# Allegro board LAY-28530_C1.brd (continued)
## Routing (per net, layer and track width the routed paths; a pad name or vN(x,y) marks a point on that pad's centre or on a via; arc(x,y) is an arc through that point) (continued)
DDR4_BA0: length 137
  TOP w0.127: v2(130.32,19.3) 130.72,19.7 U35.K2 ; v2(158.26,19.3) 158.66,19.7 U37.K2
  TOP w0.152: v2(144.29,19.3) 144.69,19.7 U36.K2 ; v2(116.35,19.3) 116.75,19.7 U34.K2
  TOP w0.178: U21.AC21 132.2,56.81 131.88,56.81 131.37,56.31 131.37,51.74 v1(134.68,48.44)
  L4_INT2 w0.127: v1(167.7,20.62) 166.93,19.86 158.93,19.86 158.37,19.3 v2(158.26,19.3) 157.83,19.73 156.77,19.73 156.65,19.61 156.65,19.48 156.52,19.35 156.14,19.35 156.01,19.48 156.01,19.61 155.89,19.73 144.73,19.73 v2(144.29,19.3) 144.26,19.3 143.82,19.73 130.76,19.73 v2(130.32,19.3) 129.89,19.73 125.79,19.73 125.66,19.61 125.66,19.48 125.53,19.35 125.15,19.35 125.02,19.48 125.02,19.61 124.9,19.73 116.79,19.73 v2(116.35,19.3) 115.92,19.73 114.86,19.73
  L4_INT2 w0.178: 114.86,19.73 113.72,20.88 113.72,28.88 118.55,33.7 125.02,33.7 126.29,34.97 129.17,34.97 129.34,34.8 129.34,34.54 129.17,34.37 127.02,34.37 126.72,34.06 126.72,33.78 126.89,33.6 127.99,33.6 128.2,33.4 128.2,33.12 128.02,32.94 126.47,32.94 126.29,32.76 126.29,32.48 126.47,32.31 128.58,32.31 131.63,35.35 135.95,35.35 137.72,37.13 139.76,37.13 140.01,37.39 140.01,44.12 139.38,44.75 135.57,44.75 134.73,45.59 134.73,48.38 v1(134.68,48.44)
  BOTTOM w0.152: R383.2 168.84,20.11 168.2,20.11 v1(167.7,20.62)
DDR4_BA1: length 131.5
  TOP w0.127: U35.K8 135.52,19.7 v2(135.92,19.3) ; v2(163.86,19.3) 163.46,19.7 U37.K8 ; 133.41,54.66 133.41,56.42 133.8,56.81 U21.AA21
  TOP w0.152: U34.K8 121.55,19.7 v2(121.95,19.3) ; v2(149.89,19.3) 149.49,19.7 U36.K8 ; R173.2 v1(168.59,21.64)
  TOP w0.178: v1(133.79,54.02) 133.41,54.4 133.41,54.66
  L3_INT1 w0.127: 114.26,19.7 121.55,19.7 v2(121.95,19.3) 122.39,19.73 124.9,19.73 125.02,19.61 125.02,19.35 125.15,19.23 125.66,19.23 125.79,19.35 125.79,19.48 126.01,19.7 135.29,19.7 135.38,19.61 135.61,19.61 v2(135.92,19.3) 135.94,19.28 135.94,19.31 136.36,19.73 149.46,19.73 v2(149.89,19.3) 150.33,19.73 151.95,19.73 152.08,19.61 152.08,19.48 152.2,19.35 152.46,19.35 152.58,19.48 152.58,19.61 152.71,19.73 156.01,19.73 156.27,19.99 163.17,19.99 v2(163.86,19.3) 163.88,19.28 163.88,19.34 164.27,19.73 165.28,19.73 166.68,21.13 168.08,21.13 v1(168.59,21.64)
  L3_INT1 w0.178: 114.26,19.7 111.94,22.02 111.94,30.78 120.07,38.91 120.07,40.69 121.47,42.09 125.36,42.09 125.56,42.29 125.56,42.54 125.38,42.72 122.74,42.72 122.48,42.97 122.48,43.15 122.66,43.33 125.86,43.33 126.04,43.51 126.04,43.69 125.86,43.86 123.83,43.86 123.65,44.04 123.65,44.3 123.83,44.47 127.26,44.47 127.44,44.65 127.44,44.83 127.26,45.01 124.95,45.01 124.77,45.18 124.77,45.44 124.95,45.62 127.9,45.62 128.07,45.79 128.07,45.97 127.9,46.15 126.09,46.15 125.91,46.33 125.91,46.61 126.09,46.78 128.71,46.78 132.01,50.09 132.01,52.37 133.66,54.02 v1(133.79,54.02)
DDR4_BG0: length 137.3
  TOP w0.127: U37.J2 158.66,20.5 v2(159.06,20.9) ; U35.J2 130.72,20.5 v2(131.12,20.9) ; U34.J2 116.75,20.5 v2(117.15,20.9) ; v2(145.09,20.9) 144.69,20.5 U36.J2 ; U21.R18 138.6,59.21 v2(138.19,58.81)
  L4_INT2 w0.127: v2(138.19,58.81) 138.59,58.41 139.96,58.41 140.2,58.17 140.2,54.84 ; 114.61,21.23 114.61,21.13 115.25,20.5 116.75,20.5 v2(117.15,20.9) 117.64,21.38 119.94,21.38 120.85,20.48 130.7,20.48 v2(131.12,20.9) 131.61,21.38 133.66,21.38 134.55,20.5 U36.J2 v2(145.09,20.9) 145.58,21.38 147.5,21.38 148.39,20.5 U37.J2 v2(159.06,20.9) 159.06,21 159.44,21.38 161.73,21.38 162.62,20.5 165.54,20.5 v1(167.7,22.65)
  L4_INT2 w0.178: 114.61,21.23 114.61,27.73 118.04,31.16 126.88,31.16 127.06,30.99 127.06,30.73 126.88,30.55 124.31,30.55 124.14,30.38 124.14,30.2 124.31,30.02 127.95,30.02 132.26,34.34 136.33,34.34 138.11,36.12 140.52,36.12 141.03,36.62 141.03,45.13 140.39,45.77 136.07,45.77 135.82,46.02 135.82,48.05 136.96,49.2 138.87,49.2 139.38,49.71 139.38,54.02 140.2,54.84
  BOTTOM w0.152: v1(167.7,22.65) 168.2,22.15 168.84,22.15 R380.2
DDR4_BG1: length 131.8
  TOP w0.122: 121.58,20.5 121.57,20.5 U34.J8
  TOP w0.127: v2(137.4,58.81) 137.8,59.21 U21.T18 ; v2(135.92,20.9) 135.52,20.5 U35.J8 ; U36.J8 149.49,20.5 v2(149.89,20.9) ; 121.58,20.5 v2(121.95,20.88) ; v2(163.86,20.9) 163.46,20.5 U37.J8
  TOP w0.152: R170.2 v1(168.59,23.67)
  L3_INT1 w0.127: v1(168.59,23.67) 168.08,23.16 167.57,23.16 164.78,20.37 164.39,20.37 v2(163.86,20.9) 163.63,20.9 163.23,21.3 161.01,21.3 160.21,20.5 150.3,20.5 149.89,20.9 v2(149.89,20.9) 149.66,20.9 149.3,21.26 149.3,21.26 149.26,21.3 147.55,21.3 146.74,20.5 136.32,20.5 v2(135.92,20.9) 135.7,20.9 135.3,21.3 133.83,21.3 133.03,20.5 122.35,20.5 121.98,20.88 v2(121.95,20.88) 121.74,20.88 121.36,21.26 121.36,21.26 121.32,21.3 119.73,21.3 118.93,20.5 114.74,20.5 114.73,20.5 ; v2(137.4,58.81) 137.8,58.41 137.8,55.04
  L3_INT1 w0.178: 114.73,20.5 112.71,22.53 112.71,30.15 120.07,37.51 122.87,37.51 124.39,39.04 124.39,40.82 124.64,41.07 127.82,41.07 130.61,43.86 131.37,43.86 132.06,44.55 132.06,45.21 131.88,45.39 131.71,45.39 131.53,45.21 131.53,44.93 131.35,44.75 131.17,44.75 130.99,44.93 130.99,45.51 132.01,46.53 132.01,46.78 131.75,47.04 131.5,47.04 130.55,46.08 130.3,46.08 130.1,46.28 130.1,46.53 133.28,49.71 133.28,51.18 133.46,51.36 133.79,51.36 133.91,51.23 133.91,49.07 134.04,48.94 134.42,48.94 134.55,49.07 134.55,50.59 134.68,50.72 136.66,50.72 136.84,50.9 136.84,51.18 136.66,51.36 134.47,51.36 134.3,51.53 134.3,51.81 134.47,51.99 135.69,51.99 136.01,52.31 136.01,53.25 137.8,55.04
DDR4_CAS: length 156.5
  TOP w0.127: U37.H7 162.66,21.3 161.47,20.11 161.47,16.43 ; 119.69,16.18 119.69,17.96 119.56,18.08 119.56,20.11 120.75,21.3 U34.H7 ; v2(135,58.81) 135.4,59.21 U21.W18 ; U35.H7 134.72,21.3 133.53,20.11 133.53,16.56 133.66,16.43 ; U36.H7 148.69,21.3 147.5,20.11 147.5,15.8 147.76,15.54
  TOP w0.152: 147.76,15.54 147.76,14.17 147.91,14.02 v1(148.14,14.02) ; v1(119.94,14.02) 119.69,14.27 119.69,16.18 ; R183.2 v1(168.59,12.11) ; v1(133.66,14.02) 133.15,14.53 133.15,14.78 133.28,14.91 133.53,14.91 133.66,15.03 133.66,16.43 ; 161.47,16.43 v1(161.47,14.02)
  L3_INT1 w0.127: v1(168.59,12.11) 168.59,12.14 168.18,12.55 167.42,12.55 165.94,14.02 v1(161.47,14.02)
  L4_INT2 w0.127: v2(135,58.81) 134.6,58.41 132.9,58.41 132.48,58 ; v1(161.47,14.02) 160.71,14.02 160.58,13.89 160.58,13.76 160.46,13.64 160.08,13.64 159.95,13.76 159.95,13.89 159.82,14.02 159.31,14.02 159.19,13.89 159.19,13.64 159.06,13.51 158.81,13.51 158.68,13.64 158.68,13.89 158.55,14.02 157.79,14.02 157.16,14.65 152.58,14.65 151.95,14.02 v1(148.14,14.02) 144.84,14.02 144.2,14.65 138.74,14.65 138.11,14.02 v1(133.66,14.02) 133.53,13.89 128.83,13.89 128.2,14.53 122.36,14.53 121.85,14.02 v1(119.94,14.02)
  L4_INT2 w0.178: 132.48,58 128.67,54.19 128.67,50.94 126.17,48.44 126.17,44.55 125.99,44.37 125.74,44.37 125.56,44.55 125.56,44.68 125.38,44.85 125.1,44.85 124.93,44.68 124.93,43.64 124.14,42.85 115.25,42.85 113.72,41.32 113.72,35.74 109.15,31.16 109.15,19.35 114.48,14.02 v1(119.94,14.02)
DDR4_CS0: length 133.7
  TOP w0.127: U36.G7 v2(148.29,22.5) ; 131.76,55.93 131.76,56.11 132.06,56.41 132.6,56.41 133,56.81 U21.AB21 ; U35.G7 v2(134.32,22.5) ; U37.G7 v2(162.26,22.5) ; U34.G7 v2(120.35,22.5)
  TOP w0.178: v1(137.85,48.05) 137.22,48.69 135.31,48.69 131.76,52.25 131.76,55.93
  L4_INT2 w0.127: 117.55,27.63 117.55,22.89 117.94,22.5 ; v1(167.7,25.7) 167.19,25.19 166.93,25.19 164.64,22.9 162.66,22.9 v2(162.26,22.5) 154.52,22.5 154.36,22.65 154.36,22.78 154.23,22.91 153.85,22.91 153.73,22.78 153.73,22.63 153.6,22.5 151.6,22.5 151.19,22.9 148.69,22.9 v2(148.29,22.5) 147.88,22.91 145.27,22.91 145.26,22.9 134.72,22.9 v2(134.32,22.5) 131.35,22.5 130.95,22.9 126.29,22.9 126.17,22.77 126.17,22.65 126.04,22.53 125.79,22.53 125.66,22.65 125.66,22.77 125.53,22.9 120.75,22.9 v2(120.35,22.5)
  L4_INT2 w0.178: 117.94,22.5 v2(120.35,22.5) ; v1(137.85,48.05) 141.92,48.05 142.55,47.42 142.55,34.72 142.3,34.47 138.99,34.47 138.87,34.34 138.87,33.96 138.99,33.83 142.37,33.83 142.55,33.65 142.55,33.37 142.37,33.2 139.25,33.2 139.12,33.07 139.12,32.69 139.25,32.56 140.98,32.56 141.15,32.38 141.15,32.1 140.98,31.93 132.52,31.93 128.96,28.37 118.29,28.37 117.55,27.63
  BOTTOM w0.152: v1(167.7,25.7) 168.2,25.19 168.84,25.19 R376.2
DDR4_CS1: length 132.3
  TOP w0.127: U36.G8 v2(149.89,21.7) ; U34.G8 v2(121.95,21.7) ; U37.G8 v2(163.86,21.7) ; 131.44,58.4 131.82,58.79 133.38,58.79 133.8,59.21 U21.AA18 ; U35.G8 v2(135.92,21.7)
  TOP w0.152: R168.2 v1(168.59,25.7)
  TOP w0.178: 131.44,58.4 130.23,57.2 130.23,50.47 v1(132.77,47.93)
  L3_INT1 w0.127: v1(168.59,25.7) 168.08,25.19 167.32,25.19 166.81,24.69 166.81,23.92 164.98,22.1 164.26,22.1 v2(163.86,21.7) U37.G8 159.26,22.1 159.24,22.11 150.87,22.11 150.86,22.1 150.53,22.1 150.51,22.11 150.31,22.11 v2(149.89,21.7) 149.49,22.1 139.63,22.1 139.5,21.97 139.5,21.89 139.38,21.77 139.12,21.77 139,21.88 139,22.01 138.91,22.1 136.32,22.1 135.94,21.71 135.94,21.68 v2(135.92,21.7) 135.47,22.15 135.33,22.15 135.29,22.1 134.96,22.1 134.91,22.15 134.53,22.15 134.49,22.1 134.16,22.1 134.11,22.15 125.58,22.15 125.41,21.97 125.41,21.89 125.28,21.77 124.9,21.77 124.78,21.88 124.78,21.97 124.65,22.1 122.35,22.1 v2(121.95,21.7) U34.G8 114.79,22.1
  L3_INT1 w0.178: 114.79,22.1 113.47,23.42 113.47,29.64 119.16,35.33 123.96,35.33 124.14,35.51 124.14,35.68 123.96,35.86 120.38,35.86 120.2,36.04 120.2,36.32 120.38,36.5 123.5,36.5 124.87,37.87 127.39,37.87 127.56,38.05 127.56,38.22 127.39,38.4 125.84,38.4 125.66,38.58 125.66,38.81 125.84,38.99 128.66,38.99 128.83,39.16 128.83,39.34 128.66,39.52 125.84,39.52 125.66,39.7 125.66,39.88 125.84,40.05 128.58,40.05 131.37,42.85 131.88,42.85 133.28,44.24 133.28,47.42 v1(132.77,47.93)
DDR4_DM0: length 46
  TOP w0.127: U37.A7 v2(162.26,27.3)
  TOP w0.178: U21.A21 152.33,54.27 152.33,48.82 154.62,46.53 154.62,44.88 155.38,44.12 155.38,39.67 155.5,39.55 155.89,39.55 156.01,39.67 156.01,44.57 156.19,44.75 156.47,44.75 156.65,44.57 156.65,39.93 159.25,37.32 159.25,36.43 160.71,34.97 160.71,30.43 v1(162.26,28.88)
  L3_INT1 w0.178: v2(162.26,27.3) v1(162.26,28.88)
DDR4_DM1: length 40.5
  TOP w0.109: U21.E21 146.6,56.81 v2(147,56.41)
  TOP w0.127: U36.A7 v2(148.29,27.3)
  L3_INT1 w0.178: v2(148.29,27.3) 147.88,27.71 147.88,31.8 148.01,31.93 148.77,31.93 148.9,32.05 148.9,35.3 148.72,35.48 148.39,35.48 148.27,35.35 148.27,32.64 148.09,32.46 147.91,32.46 147.73,32.64 147.73,35.84 147.88,35.99 148.77,35.99 148.9,36.12 148.9,47.55 148.27,48.18 148.27,49.96 148.9,50.59 148.9,51.03 148.7,51.23 148.52,51.23 148.27,51.48 148.27,53.13 147.5,53.9 147.5,55.93 147.02,56.41 v2(147,56.41)
DDR4_DM2: length 41.2
  TOP w0.127: U21.H22 144.2,56.01 144.59,55.62 144.59,54.69 ; U35.A7 v2(134.32,27.3)
  TOP w0.178: 144.59,54.69 144.59,40.82 142.17,38.4 141.92,38.4 141.72,38.6 141.72,38.84 142.3,39.42 142.3,39.55 142.04,39.8 141.66,39.8 135.31,33.45 135.06,33.45 134.93,33.32 134.93,33.07 135.06,32.94 135.82,32.94 135.95,32.81 135.95,32.56 135.82,32.43 134.68,32.43 134.55,32.31 134.55,32.05 134.68,31.93 135.69,31.93 135.95,31.67 v1(135.95,31.29)
  L3_INT1 w0.178: v1(135.95,31.29) 135.95,31.16 135.44,30.66 135.44,28.72 134.32,27.61 v2(134.32,27.3)
DDR4_DM3: length 51.7
  TOP w0.127: U21.L20 141.8,57.61 v2(142.2,57.21) ; U34.A7 v2(120.35,27.3)
  L3_INT1 w0.127: 123.75,26.9 122.92,26.9 122.92,26.9 U34.A7 v2(120.35,27.3) ; 142.6,55.04 142.6,56.81 v2(142.2,57.21)
  L3_INT1 w0.178: 123.75,26.9 125.97,26.9 131.88,32.81 133.79,32.81 142.42,41.45 142.42,41.7 142.23,41.9 141.98,41.9 140.14,40.05 139.88,40.05 139.63,40.31 139.63,40.56 142.6,43.53 142.6,55.04
DDR4_DQ0: length 46.3
  TOP w0.127: U37.C2 v2(159.06,24.9)
  TOP w0.178: U21.A19 149.86,58.34 150.93,58.34 156.01,53.26 156.01,52.75 155.89,52.63 155.5,52.63 155.38,52.5 155.38,52.12 155.5,51.99 155.89,51.99 156.01,51.86 156.01,51.61 155.76,51.36 155.63,51.36 155.38,51.1 155.38,49.71 161.85,43.23 161.85,38.28 163.76,36.37 163.76,31.04 v1(162.87,30.15)
  L3_INT1 w0.178: v2(159.06,24.9) 159.53,24.43 161.85,24.43 162.87,25.45 v1(162.87,30.15)
DDR4_DQ1: length 46.4
  TOP w0.127: 150.42,56.82 150.04,57.2 148.61,57.2 U21.C20 ; U37.B7 v2(162.26,26.5)
  TOP w0.178: 150.42,56.82 152.96,54.28 152.96,49.07 157.28,44.75 157.28,40.18 157.46,40 157.74,40 157.92,40.18 157.92,43.69 158.1,43.86 158.38,43.86 158.55,43.69 158.55,39.29 159.82,38.02 159.82,36.88 161.35,35.35 161.35,30.66 v1(161.73,30.27)
  L3_INT1 w0.178: v2(162.26,26.5) 161.73,27.03 v1(161.73,30.27)
DDR4_DQ2: length 46.1
  TOP w0.127: U37.D3 v2(159.86,24.9)
  TOP w0.178: U21.C23 150.93,52.47 150.93,48.31 151.69,47.55 151.69,44.37 151.82,44.24 152.2,44.24 152.33,44.37 152.33,46.23 152.51,46.4 152.79,46.4 152.96,46.23 152.96,39.8 153.35,39.42 153.98,39.42 155.5,37.89 155.5,37.39 156.78,36.11 157.03,36.11 157.29,36.37 157.29,36.62 156.33,37.58 156.33,37.83 156.52,38.02 156.77,38.02 158.04,36.75 158.04,35.61 159.19,34.47 159.19,29.39 v1(159.95,28.62)
  L3_INT1 w0.178: v1(159.95,28.62) 160.33,28.24 160.33,25.37 v2(159.86,24.9)
DDR4_DQ3: length 46.1
  TOP w0.178: U37.D7 162.42,24.5 160.84,26.08 160.84,26.97 159.06,28.75 v1(157.03,28.75) ; U21.D23 147.39,55.21 147.39,54.01 149.28,52.12 149.28,48.05 150.55,46.78 150.55,40.23 150.73,40.05 151.01,40.05 151.19,40.23 151.19,41.53 151.36,41.7 151.69,41.7 151.82,41.58 151.82,37.39 154.23,34.97 155.33,34.97 155.63,34.67 155.63,33.45 155.76,33.32 156.14,33.32 156.27,33.45 156.27,34.67 156.44,34.85 156.72,34.85 156.9,34.67 v1(156.9,32.18)
  L3_INT1 w0.178: v1(157.03,28.75) 156.9,28.88 v1(156.9,32.18)
DDR4_DQ4: length 46.5
  TOP w0.127: U37.D2 v2(159.06,24.1) ; U21.B19 149.4,58 150.3,58
  TOP w0.178: v1(163,31.93) 163,35.86 161.09,37.77 161.09,42.85 154.74,49.2 154.74,53.77 150.51,58 150.3,58
  L3_INT1 w0.127: v2(159.06,24.1) 159.11,24.05 163.12,24.05 164.26,25.19 164.26,27.86 164.27,27.86
  L3_INT1 w0.178: 164.27,27.86 164.27,28.12 163.89,28.5 163.89,31.04 v1(163,31.93)
DDR4_DQ5: length 46.3
  TOP w0.127: U37.D8 v2(163.06,24.9)
  TOP w0.178: U21.A20 149.8,57.61 150.27,57.61 154.11,53.77 154.11,48.82 159.06,43.86 159.06,39.67 159.19,39.55 159.57,39.55 159.7,39.67 159.7,42.67 159.87,42.85 160.22,42.85 160.39,42.67 160.39,37.32 162.24,35.48 162.24,31.8 v1(163,31.04)
  L3_INT1 w0.178: v1(163,31.04) 163.38,30.66 163.38,25.22 v2(163.06,24.9)
DDR4_DQ6: length 46
  TOP w0.127: v2(160.71,24.95) U37.E3
  TOP w0.178: v1(159.95,29.64) 159.95,34.72 158.68,35.99 158.68,37.01 156.9,38.78 155.38,38.78 154.74,39.42 154.74,43.94 154.57,44.12 154.29,44.12 154.11,43.94 154.11,40.31 153.98,40.18 153.6,40.18 153.47,40.31 153.47,46.66 151.57,48.56 151.57,52.64 U21.B23
  L3_INT1 w0.178: v2(160.71,24.95) 160.71,28.88 v1(159.95,29.64)
DDR4_DQ7: length 46
  TOP w0.127: U21.D22 147.39,56.01 147.79,55.62 147.79,54.66
  TOP w0.178: U37.E7 160.46,25.9 160.46,26.72 159.06,28.12 v1(158.3,28.12) ; 147.79,54.66 147.79,54.4 150.3,51.9 150.3,48.18 151.19,47.29 151.19,43.86 152.33,42.72 152.33,37.77 154.36,35.73 154.61,35.73 154.87,35.99 154.87,36.24 153.35,37.77 153.35,38.02 153.54,38.21 153.79,38.21 156.52,35.48 157.16,35.48 157.79,34.85 v1(157.79,32.69)
  L3_INT1 w0.178: v1(158.3,28.12) 157.79,28.62 v1(157.79,32.69)
DDR4_DQ8: length 40.6
  TOP w0.109: U21.C21 v2(148.6,56.41)
  TOP w0.127: U36.C2 v2(144.29,24.9)
  L3_INT1 w0.127: v2(148.6,56.41) 148.2,56.01 148.2,55.11 ; v2(144.29,24.9) 144.69,24.5 145.26,24.5 145.32,24.43 149.19,24.43 149.49,24.73 149.49,25.19
  L3_INT1 w0.178: 148.2,55.11 148.52,54.79 148.52,54.4 149.79,53.13 149.79,52.75 149.66,52.63 149.41,52.63 149.28,52.5 149.28,52.12 149.41,51.99 149.66,51.99 149.79,51.86 149.79,49.96 149.28,49.45 149.28,48.56 149.79,48.05 149.79,28.37 149.28,27.86 149.28,25.4 149.49,25.19
DDR4_DQ9: length 40.5
  TOP w0.127: U36.B7 v2(148.29,26.5)
  TOP w0.152: v2(147,57.21) 146.99,57.21 U21.E20
  L3_INT1 w0.127: 147,57.2 146.6,56.8 146.6,55.06
  L3_INT1 w0.178: v2(148.29,26.5) 147.25,27.54 147.25,36.24 147.5,36.5 148.14,36.5 148.39,36.75 148.39,39.04 148.27,39.16 147.88,39.16 147.76,39.04 147.76,37.16 147.58,36.98 147.4,36.98 147.22,37.16 147.22,39.67 147.35,39.8 148.27,39.8 148.39,39.93 148.39,47.29 147.76,47.93 147.76,50.21 148.14,50.59 148.14,50.98 147.76,51.36 147.76,52.88 147,53.64 147,54.66 146.6,55.06 ; v2(147,57.21) 147,57.2
DDR4_DQ10: length 40.5
  TOP w0.127: U36.D3 v2(145.09,24.9) ; U21.H21 144.2,56.81 v2(144.6,56.41)
  L3_INT1 w0.127: 145.09,54.91 144.74,55.27 144.74,56.27 v2(144.6,56.41)
  L3_INT1 w0.178: 145.09,54.91 145.09,53.13 145.98,52.25 145.98,47.17 146.36,46.78 146.36,45.82 146.18,45.64 145.47,45.64 144.96,45.13 144.96,39.8 145.34,39.42 145.34,33.45 145.22,33.32 144.2,33.32 144.07,33.2 144.07,31.09 144.25,30.91 144.53,30.91 144.71,31.09 144.71,32.69 144.84,32.81 145.22,32.81 145.34,32.69 145.34,27.73 145.09,27.48 v2(145.09,24.9)
DDR4_DQ11: length 40.7
  TOP w0.127: v2(143.8,56.41) 143.4,56.81 U21.J21
  TOP w0.178: v2(143.95,28.62) 145.22,28.62 147.76,26.08 147.76,25.43 U36.D7
  L3_INT1 w0.127: v2(143.8,56.41) 143.8,56.17 144.2,55.77 144.2,55.04 143.95,54.79
  L3_INT1 w0.178: 143.95,54.79 143.95,52.63 144.96,51.61 144.96,46.91 143.95,45.9 143.95,39.29 144.33,38.91 144.33,35.53 144.15,35.35 143.87,35.35 143.69,35.53 143.69,36.5 143.57,36.62 143.19,36.62 143.06,36.5 143.06,34.08 142.55,33.58 142.55,30.99 143.95,29.59 v2(143.95,28.62)
DDR4_DQ12: length 40.8
  TOP w0.127: v2(147.8,58.01) 147.4,58.41 147.39,58.41 U21.D19 ; U36.D2 v2(145.09,24.1)
  L3_INT1 w0.127: 149,55.04 149,56.81 v2(147.8,58.01) ; v2(145.09,24.1) 145.14,24.05 149.28,24.05 150.29,25.07 150.29,27.73
  L3_INT1 w0.178: 150.29,27.73 150.29,53.39 149,54.69 149,55.04
DDR4_DQ13: length 40.6
  TOP w0.109: U21.D21 147.39,56.81 147.4,56.81 v2(147.8,56.41)
  TOP w0.127: U36.D8 v2(149.09,24.9)
  L3_INT1 w0.178: v2(149.09,24.9) 148.77,25.22 148.77,27.99 149.41,28.62 149.41,30.78 149.28,30.91 149.03,30.91 148.9,30.78 148.9,28.7 148.72,28.52 148.55,28.52 148.37,28.7 148.37,31.18 148.6,31.42 149.28,31.42 149.41,31.54 149.41,47.8 148.77,48.44 148.77,49.71 149.28,50.21 149.28,51.48 149.15,51.61 148.9,51.61 148.77,51.74 148.77,53.39 147.88,54.28 147.88,56.32 v2(147.8,56.41)
DDR4_DQ14: length 40.6
  TOP w0.127: U36.E3 v2(146.74,24.95)
  TOP w0.152: U21.G20 145,57.61 v2(144.6,57.21)
  L3_INT1 w0.127: 145.47,54.91 145,55.39 145,56.81 v2(144.6,57.21) ; 145.49,25.18 145.85,24.81 146.6,24.81 v2(146.74,24.95)
  L3_INT1 w0.178: 145.47,54.91 145.49,54.89 145.49,53.37 146.49,52.37 146.49,47.29 147,46.78 147,43.91 146.82,43.74 146.54,43.74 146.36,43.91 146.36,44.83 146.18,45.01 145.85,45.01 145.73,44.88 145.73,43.21 145.49,42.97 145.49,39.91 145.85,39.55 145.85,27.59 145.49,27.23 145.49,25.18
DDR4_DQ15: length 40.5
  TOP w0.152: v2(143.8,57.21) 143.4,57.61 U21.J20
  TOP w0.178: v1(144.58,27.99) 145.22,27.99 147.25,25.96 147.25,25.14 U36.E7
  L3_INT1 w0.127: 144.46,54.91 144.46,55.98 144.2,56.24 144.2,56.57 144.2,56.58 144.2,56.8 v2(143.8,57.21)
  L3_INT1 w0.178: v1(144.58,27.99) 144.58,29.77 143.38,30.97 143.38,33.51 143.69,33.83 143.69,34.47 143.82,34.59 144.18,34.59 144.3,34.47 144.3,34.26 144.48,34.08 144.66,34.08 144.84,34.26 144.84,39.16 144.46,39.55 144.46,45.51 145.09,46.15 145.6,46.15 145.85,46.4 145.85,46.66 145.47,47.04 145.47,51.86 144.46,52.88 144.46,54.91
DDR4_DQ16: length 41.6
  TOP w0.127: U35.C2 v2(130.32,24.9) ; 146.2,54.66 146.2,55.6 145.8,56.01 U21.F22
  TOP w0.178: 146.2,54.66 146.2,39.89 136.71,30.4 v1(135.95,30.4)
  L3_INT1 w0.127: v2(130.32,24.9) 130.32,24.85 130.67,24.5 131.57,24.5
  L3_INT1 w0.178: v1(135.95,30.4) 135.95,28.62 134.93,27.61 134.93,25.58 133.76,24.41 131.66,24.41 131.57,24.5
DDR4_DQ17: length 41.5
  TOP w0.127: U35.B7 v2(134.32,26.5)
  TOP w0.178: U21.G23 145,55.21 145.09,55.12 145.09,40.56 139.88,35.35 139.63,35.35 139.44,35.55 139.44,35.8 141.28,37.64 141.28,37.77 140.96,38.09 140.71,38.09 136.71,34.08 v1(136.71,32.81)
  L3_INT1 w0.178: v2(134.32,26.5) 133.79,27.03 133.79,27.75 134.93,28.9 134.93,31.04 v1(136.71,32.81)
DDR4_DQ18: length 41.1
  TOP w0.127: U35.D3 v2(131.12,24.9)
  TOP w0.178: v1(131.76,30.15) 131.76,30.53 132.01,30.78 132.39,30.78 132.52,30.91 132.52,31.29 132.39,31.42 131.88,31.42 131.76,31.54 131.76,31.93 131.88,32.05 132.26,32.05 132.39,32.18 132.39,32.43 132.26,32.56 131.88,32.56 131.76,32.69 131.76,33.07 131.88,33.2 132.26,33.2 132.39,33.32 132.39,33.7 132.26,33.83 131.88,33.83 131.76,33.96 131.76,35.86 133.15,37.26 135.82,37.26 140.52,41.96 141.92,41.96 142.42,42.47 142.42,55.04 142.6,55.21 U21.K23
  L3_INT1 w0.127: v1(131.76,30.15) 131.76,26.97 131.12,26.34 v2(131.12,24.9)
DDR4_DQ19: length 41.2
  TOP w0.127: 141.38,54.81 141.38,55.63 141,56.01 U21.M22
  TOP w0.178: 141.38,54.81 141.38,46.12 140.65,45.39 140.65,43.1 140.52,42.97 139.63,42.97 135.18,38.53 132.14,38.53 130.49,36.88 130.49,29.26 130.59,29.16 v1(130.59,29.12) ; U35.D7 133.66,25.56 133.66,26.46 132.14,27.99 130.65,27.99 v2(130.61,27.95)
  L3_INT1 w0.127: v1(130.59,29.12) 130.59,28.01 130.61,27.99 v2(130.61,27.95)
DDR4_DQ20: length 41.2
  TOP w0.127: U35.D2 v2(131.12,24.1)
  TOP w0.178: v1(136.84,29.64) 145.47,38.28 146.36,38.28 146.87,38.78 146.87,54.94 146.6,55.21 U21.E23
  L3_INT1 w0.127: 136.32,27.73 136.32,25.32 135.06,24.05 131.17,24.05 v2(131.12,24.1)
  L3_INT1 w0.178: v1(136.84,29.64) 136.84,28.24 136.32,27.73
DDR4_DQ21: length 41.3
  TOP w0.127: U35.D8 v2(135.12,24.9)
  TOP w0.178: U21.F23 145.8,55.21 145.6,55.01 145.6,40.18 138.23,32.81 137.98,32.81 137.72,33.07 137.72,33.32 139.12,34.72 139.12,34.85 138.87,35.1 138.61,35.1 137.22,33.7 137.22,31.67 v1(136.84,31.29)
  L3_INT1 w0.178: v1(136.84,31.29) 136.84,30.53 136.33,30.02 136.33,28.5 135.44,27.61 135.44,25.22 v2(135.12,24.9)
DDR4_DQ22: length 41.2
  TOP w0.127: U35.E3 132.63,24.81 132.75,24.81 v2(132.77,24.83) ; U21.K22 142.6,56.01 143,55.6 143,54.53
  TOP w0.178: 143,54.53 143,41.78 142.55,41.32 140.77,41.32 136.07,36.62 133.79,36.62 133.03,35.86 133.03,29.89 v1(132.26,29.13)
  L3_INT1 w0.127: v2(132.77,24.83) 131.87,24.83 131.53,25.17 131.53,26.24 132.26,26.97 v1(132.26,29.13)
DDR4_DQ23: length 41.3
  TOP w0.178: v1(131.21,29.46) 131.21,29.55 131.12,29.64 131.12,36.37 132.64,37.89 135.57,37.89 140.14,42.47 141.41,42.47 141.92,42.97 141.92,44.63 141.79,44.75 141.41,44.75 141.28,44.88 141.28,45.26 141.41,45.39 141.66,45.39 141.92,45.64 141.92,55.09 141.8,55.21 U21.L23 ; v2(131.21,27.48) 131.88,27.48 133.15,26.21 133.15,25.27 U35.E7
  L3_INT1 w0.127: v1(131.21,29.46) v2(131.21,27.48)
DDR4_DQ24: length 51.4
  TOP w0.127: U34.C2 v2(116.35,24.9) ; U21.K21 142.6,56.81 v2(143,56.41)
  L3_INT1 w0.127: v2(116.35,24.9) 116.35,24.85 116.7,24.5 117.59,24.5 117.68,24.41 121.32,24.41 122.21,25.3 123.23,25.3
  L3_INT1 w0.178: 123.23,25.3 123.61,25.3 123.75,25.45 123.75,25.96 123.88,26.08 124.26,26.08 124.39,25.96 124.39,25.43 124.52,25.3 125.13,25.3 132.14,32.31 134.04,32.31 143,41.26 v2(143,56.41)
DDR4_DQ25: length 51.6
  TOP w0.127: v2(142.2,56.41) 141.8,56.81 U21.L21
  TOP w0.152: U34.B7 v2(120.35,26.5)
  L3_INT1 w0.127: 142.2,56.33 142.2,56.21 141.66,55.67
  L3_INT1 w0.178: v2(142.2,56.41) 142.2,56.33 ; 141.66,55.67 141.66,43.36 136.58,38.27 136.58,38.02 136.84,37.77 136.96,37.77 138.93,39.74 139.18,39.74 139.38,39.54 139.38,39.29 133.41,33.32 131.63,33.32 126.17,27.86 120.07,27.86 119.82,27.61 119.82,27.03 v2(120.35,26.5)
DDR4_DQ26: length 51.7
  TOP w0.127: U34.D3 v2(117.15,24.9) ; U21.N21 140.2,56.81 v2(139.8,56.41)
  L3_INT1 w0.178: v2(139.8,56.41) 139.8,54.95 139.25,54.4 139.25,44.5 138.99,44.24 138.82,44.24 138.64,44.42 138.64,45.08 138.46,45.26 138.28,45.26 138.11,45.08 138.11,43.48 132.9,38.28 132.9,36.62 132.2,35.93 130.55,35.93 125.91,31.29 124.52,31.29 124.39,31.42 124.39,31.67 124.26,31.8 123.88,31.8 123.75,31.67 123.75,31.42 123.63,31.29 123.25,31.29 123.12,31.42 123.12,31.8 122.99,31.93 122.61,31.93 122.48,31.8 122.48,31.42 122.36,31.29 121.98,31.29 121.85,31.42 121.85,31.75 121.67,31.93 121.34,31.93 121.21,31.8 121.21,31.54 120.96,31.29 119.31,31.29 117.53,29.51 117.53,27.1 117.15,26.72 v2(117.15,24.9)
DDR4_DQ27: length 51.6
  TOP w0.127: v2(138.99,56.41) 139.4,56.81 U21.P21
  TOP w0.178: v2(117.02,27.48) 116.52,27.99 116.52,28.5 116.77,28.75 117.53,28.75 119.56,26.72 119.56,25.69 U34.D7
  L3_INT1 w0.127: v2(138.99,56.41) 138.6,56.01 138.6,55.28 138.36,55.04
  L3_INT1 w0.178: v2(117.02,27.48) 116.52,27.99 116.52,29.77 119.82,33.07 126.04,33.07 129.85,36.88 130.36,36.88 130.74,37.26 130.74,37.51 130.61,37.64 130.61,37.89 130.74,38.02 130.99,38.02 131.12,37.89 131.5,37.89 131.76,38.15 131.76,38.78 137.03,44.05 137.03,48.5 138.36,49.83 138.36,55.04
DDR4_DQ28: length 51.7
  TOP w0.127: v2(143,58.01) 142.6,58.41 U21.K19 ; U34.D2 v2(117.15,24.1)
  L3_INT1 w0.127: 123.18,24.5 121.73,24.5 121.28,24.05 117.2,24.05 v2(117.15,24.1) ; v2(143,58.01) 143.39,57.61 143.39,55.17 143.4,55.17
  L3_INT1 w0.178: 143.4,55.17 143.4,40.77 134.42,31.8 132.52,31.8 125.22,24.5 123.18,24.5
DDR4_DQ29: length 51.7
  TOP w0.127: U21.L19 141.8,58.41 v2(142.2,58.01) ; U34.D8 v2(121.15,24.9)
  L3_INT1 w0.127: 141.28,55.67 141.79,56.18 141.79,57.6 v2(142.2,58.01)
  L3_INT1 w0.178: v2(121.15,24.9) 120.49,24.9 119.44,25.96 119.44,27.86 119.94,28.37 125.79,28.37 131.37,33.96 133.15,33.96 136.2,37.01 136.2,37.26 136.01,37.45 135.76,37.45 135.25,36.94 134.99,36.94 134.8,37.13 134.8,37.39 141.28,43.86 141.28,55.67
DDR4_DQ30: length 51.7
  TOP w0.127: v2(118.93,24.81) 118.66,24.81 U34.E3 ; v2(139.8,57.21) 140.2,57.61 U21.N20
  L3_INT1 w0.127: v2(139.8,57.21) 140.2,56.81 140.2,55.55 140.19,55.55
  L3_INT1 w0.178: 140.19,55.55 140.19,54.71 139.63,54.15 139.63,44.24 133.41,38.02 133.41,36.24 132.58,35.42 130.8,35.42 126.04,30.66 120.58,30.66 120.45,30.53 120.45,30.02 120.33,29.89 119.82,29.89 119.69,30.02 119.69,30.53 119.56,30.66 119.31,30.66 117.91,29.26 117.91,26.97 117.55,26.61 117.55,25.18 117.91,24.81 v2(118.93,24.81)
DDR4_DQ31: length 51.6
  TOP w0.127: U21.N19 140.2,58.41 v2(139.8,58.01)
  TOP w0.178: v2(117.02,28.12) 117.4,28.12 118.93,26.59 118.93,25.52 U34.E7
  L3_INT1 w0.127: 139.8,58 139.39,57.6 139.39,55.44 139.38,55.43 139.38,55.17
  L3_INT1 w0.178: 139.38,55.17 138.87,54.66 138.87,48.31 137.72,47.17 137.72,46.66 137.85,46.53 138.36,46.53 138.49,46.4 138.49,46.02 138.36,45.9 137.85,45.9 137.6,45.64 137.6,43.74 132.39,38.53 132.39,37.64 131.12,36.37 130.23,36.37 126.29,32.43 119.82,32.43 117.02,29.64 v2(117.02,28.12) ; v2(139.8,58.01) 139.8,58
DDR4_DQS0: length 46.1
  TOP w0.127: U37.C3 v2(159.86,25.7)
  TOP w0.152: U21.B22 v2(149.4,55.61)
  L3_INT1 w0.129: v2(149.4,55.61) 149.67,55.89 150.11,55.89 150.37,55.63 150.38,55.63 151.83,54.18 151.82,54.17 151.82,44.27 152.1,44 152.68,44 152.95,44.27 152.95,48.44 153.08,48.57 153.48,48.57 153.61,48.44 153.61,44.27 159.03,38.85 159.03,27.74 159.02,27.73 159.02,26.25 159.22,26.04 159.23,26.04 159.3,25.98 159.58,25.98 v2(159.86,25.7)
DDR4_DQS0_N: length 46
  TOP w0.109: U21.B21 v2(149.4,56.41)
  TOP w0.127: U37.B3 v2(159.86,26.5)
  L3_INT1 w0.129: v2(159.86,26.5) 159.58,26.22 159.4,26.22 159.27,26.35 159.27,38.95 153.85,44.37 153.85,48.54 153.58,48.82 152.98,48.82 152.71,48.54 152.71,44.4 152.58,44.27 152.21,44.27 152.08,44.4 152.08,54.28 150.22,56.13 149.67,56.13 v2(149.4,56.41)
DDR4_DQS1: length 40.6
  TOP w0.127: U36.C3 v2(146.08,25.3) ; U21.G21 145,56.81 v2(145.4,57.21)
  L3_INT1 w0.127: v2(146.08,25.3) 146.35,25.58 147.09,25.58 147.37,25.86 147.37,26.31
  L3_INT1 w0.129: v2(145.4,57.21) 145.65,56.96 145.88,56.96 146.23,56.6 146.23,54.66 146.36,54.53 146.36,53.51 147.25,52.63 147.25,47.67 147.88,47.04 147.88,41.09 147.61,40.82 147.14,40.82 146.87,41.09 146.87,42.59 146.74,42.72 146.49,42.72 146.36,42.59 146.36,40.18 146.6,39.94 146.6,27.24 146.74,27.1 146.99,27.1 147.37,26.72 147.37,26.31
DDR4_DQS1_N: length 40.7
  TOP w0.127: U36.B3 v2(146.08,26.1)
  TOP w0.152: v2(145.4,56.41) 145.8,56.81 U21.F21
  L3_INT1 w0.127: v2(146.08,26.1) 146.35,25.82 146.99,25.82 147.12,25.96 147.12,26.31
  L3_INT1 w0.129: 147.12,26.31 147.12,26.61 146.89,26.85 146.61,26.85 146.36,26.59 146.11,26.59 146.01,26.69 146.01,26.87 146.36,27.23 146.36,39.83 146.12,40.08 146.12,42.69 146.39,42.96 146.84,42.96 147.11,42.69 147.11,41.19 147.24,41.06 147.51,41.06 147.64,41.19 147.64,46.94 147.01,47.57 147.01,52.52 146.12,53.41 146.12,54.43 145.99,54.56 145.99,56.45 145.76,56.68 145.67,56.68 v2(145.4,56.41)
DDR4_DQS2: length 41.2
  TOP w0.122: v1(133.53,30.4) 133.79,30.66 133.79,35.72 134.06,35.99 134.79,35.99 135.06,35.72 135.06,35.28 135.18,35.16 135.53,35.16 141.18,40.81 143.08,40.81 143.67,41.4 143.67,54.94 143.4,55.21 U21.J23
  TOP w0.127: U35.C3 v2(132.11,25.3)
  L3_INT1 w0.127: v2(132.11,25.3) 132.38,25.58 132.75,25.58 133.03,25.86 133.03,26.52
  L3_INT1 w0.129: v1(133.53,30.4) 133.8,30.67 133.8,30.89 133.64,31.04 133.25,31.04 133.03,30.82 133.03,29.89 133.15,29.77 133.28,29.77 133.41,29.64 133.41,29.39 133.28,29.26 133.15,29.26 133.03,29.13 133.03,27.74 133.03,27.73 133.03,26.52
DDR4_DQS2_N: length 41.1
  TOP w0.122: U21.H23 144.2,55.21 143.92,54.94 143.92,41.3 143.19,40.56 141.28,40.56 135.63,34.91 135.07,34.91 134.8,35.18 134.8,35.62 134.68,35.74 134.16,35.74 134.04,35.62 134.04,30.66 v1(134.3,30.4)
  TOP w0.127: U35.B3 v2(132.11,26.1)
  L3_INT1 w0.127: v2(132.11,26.1) 132.38,25.82 132.64,25.82 132.78,25.96 132.78,26.62
  L3_INT1 w0.129: 132.78,26.62 132.78,30.92 133.15,31.29 133.74,31.29 134.04,30.99 134.04,30.66 v1(134.3,30.4)
DDR4_DQS3: length 51.3
  TOP w0.127: U34.C3 v2(118.14,25.3) ; U21.M19 141,58.41 v2(140.6,58.01)
  L3_INT1 w0.127: v2(118.14,25.3) 118.41,25.58 118.7,25.58 118.97,25.85 118.97,26.44 118.93,26.48
  L3_INT1 w0.129: 118.93,26.48 118.93,28.02 119.91,29 121.57,29 121.84,29.28 121.84,29.77 121.97,29.9 122.26,29.9 122.39,29.77 122.39,29.28 122.66,29 123.47,29 123.74,29.28 123.74,29.82 123.87,29.95 124.21,29.95 124.34,29.82 124.34,29.28 124.61,29 125.62,29 131.22,34.6 133.04,34.6 133.1,34.66 134.17,35.74 134.17,37.68 140.85,44.36 140.85,54.28 140.87,54.3 140.87,54.51 140.86,54.52 140.86,55.74 141.44,56.32 141.44,57.21 141.04,57.61 140.99,57.61 v2(140.6,58.01)
DDR4_DQS3_N: length 51.3
  TOP w0.127: U34.B3 v2(118.14,26.1)
  TOP w0.152: U21.M20 141,57.61 v2(140.6,57.21)
  L3_INT1 w0.127: 118.68,26.58 118.68,26.58 118.68,26.38 118.72,26.34 118.72,25.95 118.59,25.82 118.41,25.82 v2(118.14,26.1)
  L3_INT1 w0.129: v2(140.6,57.21) 140.74,57.36 140.93,57.36 141.18,57.11 141.18,56.43 140.6,55.85 140.6,54.41 140.61,54.4 140.61,44.46 133.93,37.78 133.93,35.84 132.93,34.85 131.12,34.85 125.52,29.25 124.71,29.25 124.58,29.38 124.58,29.92 124.31,30.19 123.77,30.19 123.5,29.92 123.5,29.38 123.37,29.25 122.76,29.25 122.63,29.38 122.63,29.88 122.36,30.15 121.87,30.15 121.6,29.88 121.6,29.38 121.47,29.25 121.09,29.25 120.96,29.38 120.96,29.51 120.83,29.64 120.58,29.64 120.45,29.51 120.45,29.39 120.32,29.25 119.81,29.25 118.69,28.13 118.69,27.87 118.55,27.73 118.42,27.73 118.29,27.61 118.29,27.35 118.42,27.23 118.55,27.23 118.68,27.1 118.68,26.58
DDR4_MCK0: length 127.5
  TOP w0.102: 135.02,54.22 135.02,55.64 135.4,56.01 U21.W22
  TOP w0.122: v1(136.33,49.45) 136.07,49.71 135.45,49.71 135.02,50.13 135.02,50.77 135.48,51.23 136.81,51.23 137.21,50.83 137.21,49.81 137.58,49.45 138.85,49.45 139.12,49.18 139.12,46.4 139.24,46.27 139.51,46.27 139.63,46.4 139.63,49.18 139.9,49.45 140.54,49.45 140.78,49.68 140.78,50.49 140.54,50.72 137.87,50.72 137.6,50.99 137.6,51.47 137.87,51.73 140.27,51.73 140.39,51.86 140.39,52.13 140.27,52.25 135.72,52.25 135.1,52.87 135.02,52.94 135.02,54.22
  TOP w0.127: U36.F7 v2(149.09,23.3) ; U35.F7 v2(135.12,23.3) ; U37.F7 v2(163.06,23.3) ; U34.F7 v2(121.15,23.3)
  L3_INT1 w0.129: v1(136.33,49.45) 136.07,49.71 135.89,49.71 135.69,49.52 135.69,47.96 134.41,46.68 134.41,43.63 125,34.22 119.32,34.22 114.22,29.12 114.22,23.64 115.09,22.77 118.66,22.77 119.06,23.16 120.67,23.16 120.81,23.02 120.87,23.02 v2(121.15,23.3) 121.15,23.15 121.28,23.02 121.71,23.02 121.98,23.29 123.72,23.29 124.23,22.78 131.54,22.78 132.04,23.28 134.52,23.28 134.72,23.08 134.91,23.08 v2(135.12,23.3) 135.12,23.15 135.25,23.02 135.84,23.02 136.11,23.29 137.57,23.29 138.07,22.78 145.47,22.78 145.98,23.29 148.49,23.29 148.7,23.09 148.95,23.09 149.09,23.23 ; v2(163.06,23.3) 163.06,23.21 162.93,23.08 162.66,23.08 162.45,23.29 160.37,23.29 159.85,22.77 152.47,22.77 151.95,23.29 149.83,23.29 149.57,23.04 149.22,23.04 149.09,23.16 149.09,23.23 ; 149.09,23.23 v2(149.09,23.3)
  BOTTOM w0.127: v2(163.06,23.3) 162.82,23.54 R379.2
DDR4_MCK0_N: length 127.8
  TOP w0.102: 135.28,54.25 135.26,54.26 135.26,55.07 135.4,55.21 U21.W23
  TOP w0.122: 135.28,54.25 135.28,54.02 135.4,53.9 135.57,53.9 135.69,53.77 135.69,53.46 135.62,53.39 135.44,53.39 135.28,53.23 135.28,53.04 135.82,52.5 140.38,52.5 140.65,52.23 140.65,51.75 140.38,51.48 137.97,51.48 137.85,51.36 137.85,51.1 137.97,50.98 140.65,50.98 141.03,50.59 141.03,49.58 140.65,49.2 140.01,49.2 139.88,49.08 139.88,46.29 139.61,46.02 139.14,46.02 138.87,46.29 138.87,49.08 138.75,49.2 137.47,49.2 136.96,49.71 136.96,50.72 136.71,50.98 135.59,50.98 135.28,50.66 135.28,50.23 135.55,49.96 136.07,49.96 v1(136.33,50.21)
  TOP w0.127: U34.F8 v2(121.15,22.5) ; U36.F8 v2(149.09,22.5) ; U35.F8 v2(135.12,22.5) ; U37.F8 v2(163.06,22.5)
  L3_INT1 w0.129: v2(163.06,22.5) 162.72,22.84 162.56,22.84 162.35,23.05 160.47,23.05 159.95,22.53 152.37,22.53 151.85,23.05 149.93,23.05 149.66,22.77 149.37,22.77 v2(149.09,22.5) 148.76,22.83 148.6,22.83 148.39,23.05 146.08,23.05 145.57,22.54 137.97,22.54 137.46,23.04 136.22,23.04 135.94,22.77 135.39,22.77 v2(135.12,22.5) 134.78,22.84 134.62,22.84 134.42,23.04 132.14,23.04 131.63,22.53 124.14,22.53 123.62,23.05 122.09,23.05 121.81,22.77 121.42,22.77 v2(121.15,22.5) 120.87,22.78 120.71,22.78 120.57,22.92 119.16,22.92 118.77,22.53 114.99,22.53 113.98,23.54 113.98,29.22 119.22,34.47 124.9,34.47 134.17,43.74 134.17,46.78 135.45,48.06 135.45,49.62 135.78,49.95 136.07,49.95 v1(136.33,50.21)
  BOTTOM w0.127: v2(163.06,22.5) 162.53,23.04 161.98,23.04 161.47,22.53 R381.1
DDR4_MCKE0: length 154.6
  TOP w0.127: 133.15,16.43 133.15,20.47 U35.G3 ; U34.G3 119.18,20.47 119.18,17.96 119.31,17.83 119.31,16.43 ; 147.12,16.43 147.12,20.47 U36.G3 ; 161.09,16.43 161.09,20.47 U37.G3
  TOP w0.152: U21.R20 138.6,57.61 v2(138.19,57.21) ; R181.2 v1(168.59,14.15) ; v1(160.84,15.8) 161.09,16.05 161.09,16.43 ; 147.12,16.43 v1(147.12,15.54) ; 133.15,16.43 v1(133.15,15.42) ; 119.31,16.43 119.31,15.89 v1(118.93,15.5)
  L3_INT1 w0.127: 131.76,58.72 132.24,59.21 138.46,59.21 138.6,59.08 138.6,57.61 v2(138.19,57.21) ; v1(118.93,15.5) 119.02,15.5 119.06,15.54 122.61,15.54 123.12,15.03 132.77,15.03 v1(133.15,15.42) 133.28,15.54 136.45,15.54 136.96,15.03 139.25,15.03 139.38,15.16 139.38,15.29 139.5,15.42 139.76,15.42 139.88,15.29 139.88,15.16 140.01,15.03 146.61,15.03 v1(147.12,15.54) 150.3,15.54 150.93,14.91 151.57,14.91 151.95,15.29 157.92,15.29 158.3,14.91 159.95,14.91 v1(160.84,15.8) 160.97,15.92 162.62,15.92 162.87,15.67 166.43,15.67 167.44,14.65 168.08,14.65 v1(168.59,14.15)
  L3_INT1 w0.178: 131.76,58.72 128.33,55.29 124.64,55.29 109.28,39.93 109.28,19.86 114.23,14.91 118.33,14.91 v1(118.93,15.5)
DDR4_MCKE1: length 137.8
  TOP w0.127: v2(136.6,58.81) 137,59.21 U21.U18 ; U34.G2 v2(116.35,21.7) ; U35.G2 v2(130.32,21.7) ; U36.G2 v2(144.29,21.7) ; U37.G2 v2(158.26,21.7)
  L4_INT2 w0.127: 141.15,55.2 141.15,58.09 140.03,59.21 137,59.21 v2(136.6,58.81) ; 116.98,28.7 115.95,27.68 115.95,22.1 v2(116.35,21.7) 116.45,21.7 116.85,22.1 124.53,22.1 124.65,21.97 124.65,21.76 124.77,21.64 125.02,21.64 125.15,21.77 125.15,21.89 125.36,22.1 129.92,22.1 v2(130.32,21.7) 130.73,22.11 131.3,22.11 131.31,22.1 143.89,22.1 v2(144.29,21.7) 144.69,22.1 152.88,22.1 153.09,21.89 153.09,21.77 153.22,21.64 153.6,21.64 153.73,21.77 153.73,21.89 153.98,22.15 157.81,22.15 v2(158.26,21.7) 158.36,21.7 158.77,22.11 162.08,22.11 162.1,22.1 164.83,22.1 164.84,22.11 165,22.11 167.57,24.69 v1(167.7,24.69)
  L4_INT2 w0.178: 141.15,55.2 141.15,53.77 142.68,52.25 142.68,48.74 142.5,48.56 142.22,48.56 142.04,48.74 142.04,50.92 141.87,51.1 141.59,51.1 141.41,50.92 141.41,48.82 141.28,48.69 137.6,48.69 137.34,48.44 137.34,47.55 137.6,47.29 141.15,47.29 142.04,46.4 142.04,35.48 141.66,35.1 138.87,35.1 138.11,34.34 138.11,33.58 137.85,33.32 133.15,33.32 128.71,28.88 117.15,28.88 116.98,28.7
  BOTTOM w0.152: R377.2 168.84,24.18 168.2,24.18 v1(167.7,24.69)
DDR4_ODT0: length 137.4
  TOP w0.127: U35.F3 131.51,22.9 v2(131.12,23.29) ; U37.F3 v2(159.06,23.3) ; U36.F3 v2(145.09,23.3) ; U34.F3 v2(117.95,23.3)
  TOP w0.152: v2(135,58.01) 135.4,58.41 U21.W19
  L4_INT2 w0.127: 141.53,54.53 141.53,58.09 140.26,59.36 140.26,59.74 139.99,60.01 135.58,60.01 135.4,59.82 U21.W19 v2(135,58.01) ; v1(167.7,26.72) 167.7,26.46 164.93,23.7 160.23,23.7 159.83,23.3 v2(159.06,23.3) 158.66,23.7 155.91,23.7 155.88,23.67 152.96,23.67 152.84,23.54 152.84,23.42 152.71,23.29 152.46,23.29 152.33,23.42 152.33,23.54 152.17,23.7 145.49,23.7 v2(145.09,23.3) 144.72,23.67 144.48,23.67 144.46,23.7 144.13,23.7 144.1,23.67 143.69,23.67 143.66,23.7 131.53,23.7 v2(131.12,23.29) 130.71,23.7 130.49,23.7 130.49,23.7 129.36,23.7 129.36,23.7 124.77,23.7 124.64,23.83 124.64,24.43 124.52,24.56 124.26,24.56 124.14,24.43 124.14,23.83 124.01,23.7 119.85,23.7 119.45,23.3 v2(117.95,23.3) 117.95,24.47 118.55,25.07
  L4_INT2 w0.178: 141.53,54.53 141.53,54.15 143.19,52.5 143.19,30.91 140.52,28.24 139.88,28.24 139.76,28.37 139.76,29.21 139.58,29.39 139.3,29.39 139.12,29.21 139.12,27.99 138.99,27.86 138.49,27.86 138.36,27.99 138.36,29.21 138.18,29.39 137.9,29.39 137.72,29.21 137.72,28.12 137.47,27.86 135.31,27.86 135.18,27.99 135.18,29.46 135.01,29.64 134.73,29.64 134.55,29.46 134.55,27.99 134.42,27.86 134.04,27.86 133.91,27.99 133.91,29.46 133.74,29.64 133.46,29.64 133.28,29.46 133.28,28.62 133.15,28.5 129.98,28.5 129.34,27.86 119.18,27.86 118.8,27.48 118.8,25.32 118.55,25.07
  BOTTOM w0.152: v1(167.7,26.72) 168.2,26.21 168.84,26.21 R375.2
DDR4_ODT1: length 137.6
  TOP w0.127: U36.F2 v2(144.29,23.3) ; U34.F2 v2(116.35,23.3) ; U37.F2 v2(158.26,23.3) ; U35.F2 v2(130.32,23.3)
  TOP w0.152: R166.2 v1(168.59,26.72)
  TOP w0.178: U21.AC20 132.2,57.61 132.04,57.61 130.99,56.56 130.99,51.23 134.42,47.8 137.34,47.8 137.72,47.42 137.72,42.52 137.55,42.34 137.37,42.34 137.19,42.52 137.19,45.08 137.01,45.26 136.84,45.26 136.66,45.08 136.66,42.39 136.48,42.21 136.25,42.21 136.07,42.39 136.07,45.08 135.9,45.26 135.72,45.26 135.54,45.08 135.54,42.39 135.36,42.21 135.18,42.21 135.01,42.39 135.01,45.59 135.18,45.77 136.71,45.77 137.09,46.15 137.09,47.04 136.96,47.17 v1(136.45,47.17)
  L3_INT1 w0.127: 115.09,23.7 115.95,23.7 v2(116.35,23.3) 116.75,23.7 126.2,23.7 126.29,23.8 126.29,24.05 126.42,24.18 126.68,24.18 126.8,24.05 126.8,23.83 126.93,23.7 129.92,23.7 v2(130.32,23.3) 130.72,23.7 143.89,23.7 v2(144.29,23.3) 144.69,23.7 151.98,23.7 152.2,23.92 152.96,23.92 153.09,23.8 153.09,23.67 153.22,23.54 153.47,23.54 153.6,23.67 153.6,23.8 153.73,23.92 156.29,23.92 156.52,23.7 157.86,23.7 v2(158.26,23.3) 158.28,23.3 158.65,23.67 158.87,23.67 158.9,23.7 164.93,23.7 167.44,26.21 168.08,26.21 v1(168.59,26.72)
  L3_INT1 w0.178: 115.09,23.7 114.86,23.92 114.86,28.88 119.56,33.58 125.15,33.58 135.82,44.24 135.82,46.53 v1(136.45,47.17)
DDR4_PAR: length 136.4
  TOP w0.127: v2(145.09,16.9) 145.49,17.3 U36.N3 ; U21.U22 137,56.01 v2(136.6,55.61) ; U35.N3 131.52,17.3 v2(131.12,16.9) ; v2(159.06,16.9) 159.46,17.3 U37.N3 ; v2(117.15,16.9) 117.55,17.3 U34.N3
  L4_INT2 w0.127: 115.25,17.32 116.73,17.32 v2(117.15,16.9) 117.57,17.32 125.15,17.32 125.28,17.19 125.28,17.07 125.41,16.94 125.66,16.94 125.79,17.07 125.79,17.19 125.91,17.32 130.7,17.32 v2(131.12,16.9) 131.54,17.32 144.67,17.32 v2(145.09,16.9) 145.51,17.32 154.36,17.32 154.49,17.19 154.49,16.94 154.62,16.81 155,16.81 155.12,16.94 155.12,17.19 155.25,17.32 158.64,17.32 v2(159.06,16.9) 159.61,17.45 166.81,17.45 v1(167.7,16.56)
  L4_INT2 w0.178: v2(136.6,55.61) 136.6,54.67 134.3,52.37 133.41,52.37 131.76,50.72 131.76,47.04 132.77,46.02 132.77,44.24 135.31,41.7 135.31,39.09 135.13,38.91 134.85,38.91 134.68,39.09 134.68,41.4 134.5,41.58 134.22,41.58 134.04,41.4 134.04,38.83 133.86,38.66 133.58,38.66 133.38,38.86 133.38,41.23 133.2,41.4 132.92,41.4 132.74,41.23 132.74,38.83 132.57,38.66 132.31,38.66 132.14,38.83 132.14,40.51 131.96,40.69 131.68,40.69 131.5,40.51 131.5,38.91 131.25,38.66 127.31,38.66 124.52,35.86 117.66,35.86 111.69,29.89 111.69,20.37 114.74,17.32 115.25,17.32
  BOTTOM w0.152: R387.2 168.84,16.05 168.2,16.05 v1(167.7,16.56)
DDR4_PAR_ERR: length 137.5
  TOP w0.127: U35.L9 136.32,18.9 137.85,17.37 137.85,16.69 ; U37.L9 164.26,18.9 165.16,18 ; U36.L9 150.29,18.9 151.13,18.9 151.69,18.34 151.69,16.94 ; v2(135,56.41) 135.4,56.81 U21.W21 ; U34.L9 122.35,18.9 123.4,17.85
  TOP w0.152: v1(165.16,15.16) 165.79,15.8 165.79,17.37 165.16,18 ; v1(123.37,15.54) 124.01,16.18 124.01,17.24 123.4,17.85 ; 137.85,16.69 137.85,15.8 v1(137.6,15.54) ; v1(151.19,15.54) 151.69,16.05 151.69,16.94
  L4_INT2 w0.127: v1(165.16,15.16) 164.65,15.67 161.47,15.67 160.84,15.03 158.93,15.03 158.43,15.54 v1(151.19,15.54) 147.88,15.54 147.38,15.03 145.22,15.03 144.71,15.54 v1(137.6,15.54) 134.04,15.54 133.41,14.91 131.37,14.91 130.74,15.54 130.1,15.54 129.98,15.42 129.98,15.29 129.85,15.16 129.6,15.16 129.47,15.29 129.47,15.42 129.34,15.54 v1(123.37,15.54)
  L4_INT2 w0.178: v1(123.37,15.54) 119.82,15.54 119.31,15.03 114.86,15.03 110.17,19.73 110.17,30.66 116.9,37.39 123.88,37.39 125.15,38.66 125.15,41.53 125.33,41.7 125.61,41.7 125.79,41.53 125.79,40.49 125.96,40.31 126.22,40.31 126.39,40.49 126.39,42.87 126.57,43.05 126.85,43.05 127.03,42.87 127.03,41.78 127.23,41.58 127.51,41.58 127.69,41.76 127.69,46.91 128.07,47.29 129.47,47.29 129.98,47.8 129.98,51.74 133.28,55.04 134.3,55.04 134.8,55.55 134.8,56.22 v2(135,56.41)
  BOTTOM w0.152: R390.2 v1(165.16,15.16)
DDR4_RAS: length 132.9
  TOP w0.127: U37.H8 163.46,21.3 v2(163.06,21.7) ; v2(135.12,21.7) 135.52,21.3 U35.H8
  TOP w0.152: v2(149.09,21.7) 149.49,21.3 U36.H8 ; R169.2 v1(168.59,24.69) ; U34.H8 121.55,21.3 v2(121.15,21.7)
  TOP w0.178: v1(132.77,47.17) 133.03,46.91 133.03,44.68 132.85,44.5 132.57,44.5 132.39,44.68 132.39,46.35 132.21,46.53 131.93,46.53 131.76,46.35 131.76,44.8 131.58,44.63 131.3,44.63 131.12,44.8 131.12,48.77 130.94,48.94 130.66,48.94 130.49,48.77 130.49,44.68 130.31,44.5 130.03,44.5 129.85,44.68 129.85,57.58 131.37,59.1 132.09,59.1 132.2,59.21 U21.AC18
  L3_INT1 w0.127: 114.95,21.3 119.23,21.3 119.63,21.7 v2(121.15,21.7) 121.3,21.7 121.7,21.3 124.22,21.3 124.39,21.13 124.39,21 124.52,20.88 124.77,20.88 124.9,21 124.9,21.13 125.07,21.3 133.32,21.3 133.72,21.7 v2(135.12,21.7) 135.3,21.7 135.7,21.3 143.66,21.3 143.76,21.4 144.02,21.4 144.13,21.3 144.46,21.3 144.56,21.4 144.82,21.4 144.93,21.3 145.26,21.3 145.36,21.4 147.27,21.4 147.57,21.7 v2(149.09,21.7) 149.11,21.71 149.29,21.71 149.62,21.38 149.64,21.38 149.73,21.3 150.06,21.3 150.14,21.38 150.44,21.38 150.53,21.3 159.49,21.3 159.88,21.7 v2(163.06,21.7) 163.3,21.7 163.46,21.53 163.7,21.3 165.2,21.3 166.93,23.04 166.93,23.54 167.57,24.18 168.08,24.18 v1(168.59,24.69)
  L3_INT1 w0.178: v1(132.77,47.17) 132.77,44.5 131.63,43.36 130.99,43.36 128.2,40.56 125.2,40.56 125.02,40.38 125.02,38.78 123.25,37.01 120.2,37.01 113.09,29.89 113.09,23.16 114.95,21.3
DDR4_VDD: length 192.3
  TOP w0.254: v1(103.31,24.69) 102.29,24.69 98.86,21.26 98.23,21.26 98.08,21.11 ; C145.1 99.62,16.56 98.48,16.56 97.93,17.11 U38.30
  TOP w0.305: U36.C7 v2(148.29,25.7) ; U35.J9 136.32,20.5 v2(136.72,20.9) ; U36.M1 143.89,18.1 v2(143.49,18.5) ; U21.R15 138.6,61.61 v2(138.19,61.21) ; U34.B2 v2(116.35,26.5) ; v2(143.8,61.21) 143.4,61.61 U21.J15 ; v2(132.6,57.21) 133,57.61 U21.AB20 ; U37.E8 v2(163.86,24.1) ; v2(135.8,55.61) 136.2,56.01 U21.V22 ; 98.08,21.11 U38.38 ; v2(143.49,20.9) 143.89,21.3 U36.H1 ; U34.H1 115.95,21.3 v2(115.55,20.9) ; U35.H1 129.92,21.3 v2(129.52,20.9) ; v2(139.8,61.21) 140.2,61.61 U21.N15 ; v2(129.52,18.5) 129.92,18.1 U35.M1 ; v2(136.72,16.9) 136.32,17.3 U35.N9 ; U34.E8 v2(121.95,24.1) ; U36.B2 v2(144.29,26.5) ; U36.B8 v2(149.89,26.5) ; U21.V18 136.2,59.21 v2(135.8,59.61) ; U34.N9 122.35,17.3 v2(122.75,16.9) ; v2(143,61.21) 142.6,61.61 U21.K15 ; U21.P15 139.4,61.61 v2(138.99,61.21) ; C114.1 120.33,29.87 119.97,29.51 v1(118.93,29.51) ; U21.V20 136.2,57.61 v2(135.8,58.01) ; U34.C9 v2(122.75,25.7) ; v2(134.2,58.01) 134.6,57.61 U21.Y20 ; v2(132.6,55.61) 133,56.01 U21.AB22 ; U36.E2 v2(144.29,24.1) ; U37.M1 157.86,18.1 v2(157.46,18.5) ; U37.E2 v2(158.26,24.1) ; v2(115.55,18.5) 115.95,18.1 U34.M1 ; U36.C1 v2(143.49,25.7) ; v2(157.46,20.9) 157.86,21.3 U37.H1 ; U37.F1 v2(157.46,23.3) ; U34.C7 v2(120.35,25.7) ; U36.N9 150.29,17.3 v2(150.69,16.9) ; U35.A1 v2(129.52,27.3) ; U36.E8 v2(149.89,24.1) ; U36.J9 150.29,20.5 v2(150.69,20.9) ; v2(164.66,20.9) 164.26,20.5 U37.J9 ; U37.F9 v2(164.66,22.5) ; v2(137.4,58.01) 137.8,58.41 U21.T19 ; U37.C7 v2(162.26,25.7) ; U37.C9 v2(164.66,25.7) ; U34.B8 v2(121.95,26.5) ; U36.C9 v2(150.69,25.7) ; U37.C1 v2(157.46,25.7) ; U35.B2 v2(130.32,26.5) ; U34.C1 v2(115.55,25.7) ; U34.J9 122.35,20.5 v2(122.75,20.9) ; U36.A1 v2(143.49,27.3) ; U34.E2 v2(116.35,24.1) ; U35.F9 v2(136.72,22.5) ; U34.F1 v2(115.55,23.3) ; U35.E8 v2(135.92,24.1) ; U21.M15 141,61.61 v2(141.4,61.21) ; v2(137.4,59.61) 137.8,60.01 U21.T17 ; U36.F1 v2(143.49,23.3) ; U35.C1 v2(129.52,25.7) ; v2(138.19,56.41) 138.6,56.81 U21.R21 ; U35.C7 v2(134.32,25.7) ; U35.B8 v2(135.92,26.5) ; U21.Y22 134.6,56.01 v2(134.2,55.61) ; U21.L15 141.8,61.61 v2(142.2,61.21) ; v2(137.4,61.21) 137.8,61.61 U21.T15 ; U37.A1 v2(157.46,27.3) ; U21.Y18 134.6,59.21 v2(134.2,59.61) ; U21.AB18 133,59.21 v2(133.4,59.61) ; U37.B2 v2(158.26,26.5) ; C117.1 v1(153.22,29.31) ; U21.P19 139.4,58.41 v2(138.99,58.01) ; C112.1 v1(166.73,29.82) ; U36.F9 v2(150.69,22.5) ; U37.N9 164.26,17.3 v2(164.66,16.9) ; U34.A1 v2(115.55,27.3) ; U37.B8 v2(163.86,26.5) ; U34.F9 v2(122.75,22.5) ; U35.C9 v2(136.72,25.7) ; U35.E2 v2(130.32,24.1) ; v2(129.52,23.3) 129.92,22.9 U35.F1
  TOP w0.381: C110.1 v1(118.93,29.51) ; C111.1 v1(165.03,29.26) ; C145.1 100.64,15.92 101.4,16.69 103.18,16.69 ; C115.1 v1(155,28.88)
  TOP w0.533: 106.15,19.3 C136.1 105.4,20.37 ; L21.2 103.61,21.61 ; L21.2 103.61,17.6 ; L21.2 104.39,19.61 ; 105.4,17.96 C143.1 ; C143.1 106.15,16.89 ; C143.1 106.15,19.02 ; 105.4,22.53 C133.1 106.15,23.59
  BOTTOM w0.254: 115.99,22.96 C529.1 115.99,23.61 ; 113.61,14.13 C587.2 114.59,14.13 ; 136.41,22.81 C532.1 137.06,22.81 ; 121.65,26.2 C494.1 122.3,26.2 ; 137.03,59.94 C445.1 137.03,59.29 ; 164.35,16.5 C571.1 165,16.5 ; 122.35,16.56 C574.1 122.35,17.21 ; 154.37,48.68 C476.1 156.13,48.68 ; 139.7,28.88 C483.1 140.58,28.88 ; 164.24,22.15 C530.1 164.24,22.8 ; 136.3,16.56 C573.1 136.3,17.21 ; 113.71,19.21 C569.1 111.96,19.21 ; 143.84,26.04 C512.1 143.19,26.04 ; 139.32,58.32 C453.1 138.67,58.32 ; 158.6,26.15 C497.1 157.95,26.15 ; 144.13,61.14 144.05,61.21 v2(143.8,61.21) ; 130.85,54.01 C468.1 130.85,52.26 ; 161.08,21.78 C535.1 ; C535.1 161.87,21.78 ; C535.1 161.08,20.99 ; C535.1 161.87,20.99 ; 130.66,26.13 C499.1 130.01,26.13 ; 150.38,20.54 C539.1 151.03,20.54 ; 130.67,24.43 C517.1 130.67,23.78 ; 136.32,20.58 C542.1 136.32,21.23 ; 145.87,52.23 C472.1 147.62,52.23 ; 116.65,24.4 C523.1 116.65,23.75 ; 153.08,52.36 C470.1 151.33,52.36 ; 115.23,18.15 C555.1 115.88,18.15 ; 131.24,57.89 C454.1 131.24,57.01 ; 115.91,26.03 115.57,25.7 v2(115.55,25.7) ; 133.98,26 C506.1 133.98,25.35 ; 112.05,14.13 C589.2 111.07,14.13 ; 137.88,61.52 C437.1 138.53,61.52 ; 135.46,51.72 R343.1 135.46,50.74 ; 141.73,61.55 C435.1 141.08,61.55 ; 116.03,14.13 C585.2 117.01,14.13 ; 138.92,28.88 C484.1 138.05,28.88 ; 149.57,26.13 C498.1 150.22,26.13 ; 157.09,20.51 C541.1 157.73,20.51 ; 129.85,26.04 C513.1 129.2,26.04 ; 150.29,22.15 C531.1 150.29,22.8 ; 110.92,14.39 C591.2 109.16,14.39 ; 141.17,28.51 C482.1 142.92,28.51 ; 143.93,23.61 C527.1 143.93,22.96 ; 143.98,26.2 C493.1 144.63,26.2 ; 138.47,56.58 C459.1 138.01,56.12 ; 142.68,61.57 C432.1 143.33,61.57 ; 116.69,26.18 C496.1 116.04,26.18 ; 138.67,61.5 C438.1 139.32,61.5 ; 121.56,24.4 C522.1 121.56,23.75 ; 164.35,20.54 C538.1 165,20.54 ; 158.64,24.43 C516.1 158.64,23.78 ; 143.14,20.59 C536.1 143.79,20.59 ; 164.19,26.18 C495.1 163.54,26.18 ; 150.29,16.59 C572.1 150.29,17.24 ; 164.35,26.04 C510.1 165,26.04 ; 135.58,24.4 C521.1 135.58,23.75 ; 142.55,61.55 C434.1 141.9,61.55 ; 162.7,26.03 C504.1 162.7,25.38 ; 136.14,59.25 C442.1 135.5,59.25 ; 119.94,25.35 C507.1 119.94,26 ; 147.9,26.03 C505.1 147.9,25.38 ; 112.34,14.13 C588.2 113.32,14.13 ; 136.38,26.06 C508.1 137.03,26.06 ; 123.09,22.81 C533.1 122.44,22.81 ; 122.44,26.04 C514.1 123.09,26.04 ; 118.4,14.13 C584.2 117.42,14.13 ; 151.03,26.04 C511.1 150.38,26.04 ; 130.85,56.55 C460.1 130.85,54.8 ; 127.13,49.19 C475.1 128,49.19 ; 163.5,24.4 C518.1 163.5,23.75 ; 139.46,61.57 C433.1 140.11,61.57 ; 154.29,46.4 C479.1 153.42,46.4 ; 144.67,24.4 C520.1 144.67,23.75 ; 125.04,51.6 C473.1 126.79,51.6 ; 148.91,52.36 C471.1 150.67,52.36 ; 149.55,24.4 C519.1 149.55,23.75 ; 157.79,25.99 C515.1 157.14,25.99 ; 122.35,21.2 C543.1 122.35,20.55 ; 137.07,61.55 C436.1 137.72,61.55 ; 115.88,20.57 C537.1 115.23,20.57 ; 136.27,26.23 C492.1 135.62,26.23 ; 114.76,14.13 C586.2 115.74,14.13
  BOTTOM w0.305: v2(143.49,18.5) 142.92,18.5 142.91,18.49 ; 157.04,18.5 v2(157.46,18.5) ; v2(122.75,20.9) C543.1 122.75,20.36 122.74,20.34 ; v2(139.8,61.21) 140.34,61.21 140.34,61.21 ; 139.38,58.47 138.99,58.09 v2(138.99,58.01) ; v2(143.49,27.3) 143.49,27.83 143.49,27.84 ; v2(157.46,23.3) 157.46,22.68 157.46,22.68 ; 166.55,12.88 166.68,13 R390.1 ; 143.47,61.57 143.8,61.24 v2(143.8,61.21) ; v2(158.26,26.5) 158.85,26.5 158.86,26.49 ; v2(134.2,59.61) 134.2,59.5 134.51,59.18 ; 147.61,25.7 147.61,25.7 v2(148.29,25.7) ; v2(137.4,61.21) 137.4,61.34 137.22,61.52 ; 130.69,24.51 130.32,24.14 v2(130.32,24.1) ; 138.74,61.52 138.99,61.26 v2(138.99,61.21) ; v2(129.52,27.3) 129.52,27.88 129.52,27.89 ; 133.4,58.99 v2(133.4,59.61) ; v2(157.46,27.3) 157.46,27.91 157.46,27.91 ; v2(143,61.21) 143,61.22 142.68,61.54 ; 129.08,18.5 v2(129.52,18.5) ; v2(129.52,20.9) 128.98,20.9 128.96,20.88 ; v2(141.4,61.21) 140.85,61.21 140.77,61.14 ; 141.81,61.59 142.2,61.21 v2(142.2,61.21) ; 137.01,59.23 137.39,59.61 v2(137.4,59.61) ; v2(129.52,23.3) 129.52,22.71 129.52,22.71 ; 135.44,59.23 135.8,59.59 v2(135.8,59.61) ; 137.98,61.52 138.19,61.3 v2(138.19,61.21) ; 115.55,27.91 v2(115.55,27.3)
  BOTTOM w0.381: R343.1 135.06,51.23
  vias: v1(103.31,23.67) v1(104.2,24.69) v1(104.2,23.67) v1(104.2,22.78) v1(105.21,24.69) v1(105.21,23.67)
